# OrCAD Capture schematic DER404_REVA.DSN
size B; title: 72V / 115mA    A19 application; rev: A; note: <Doc>
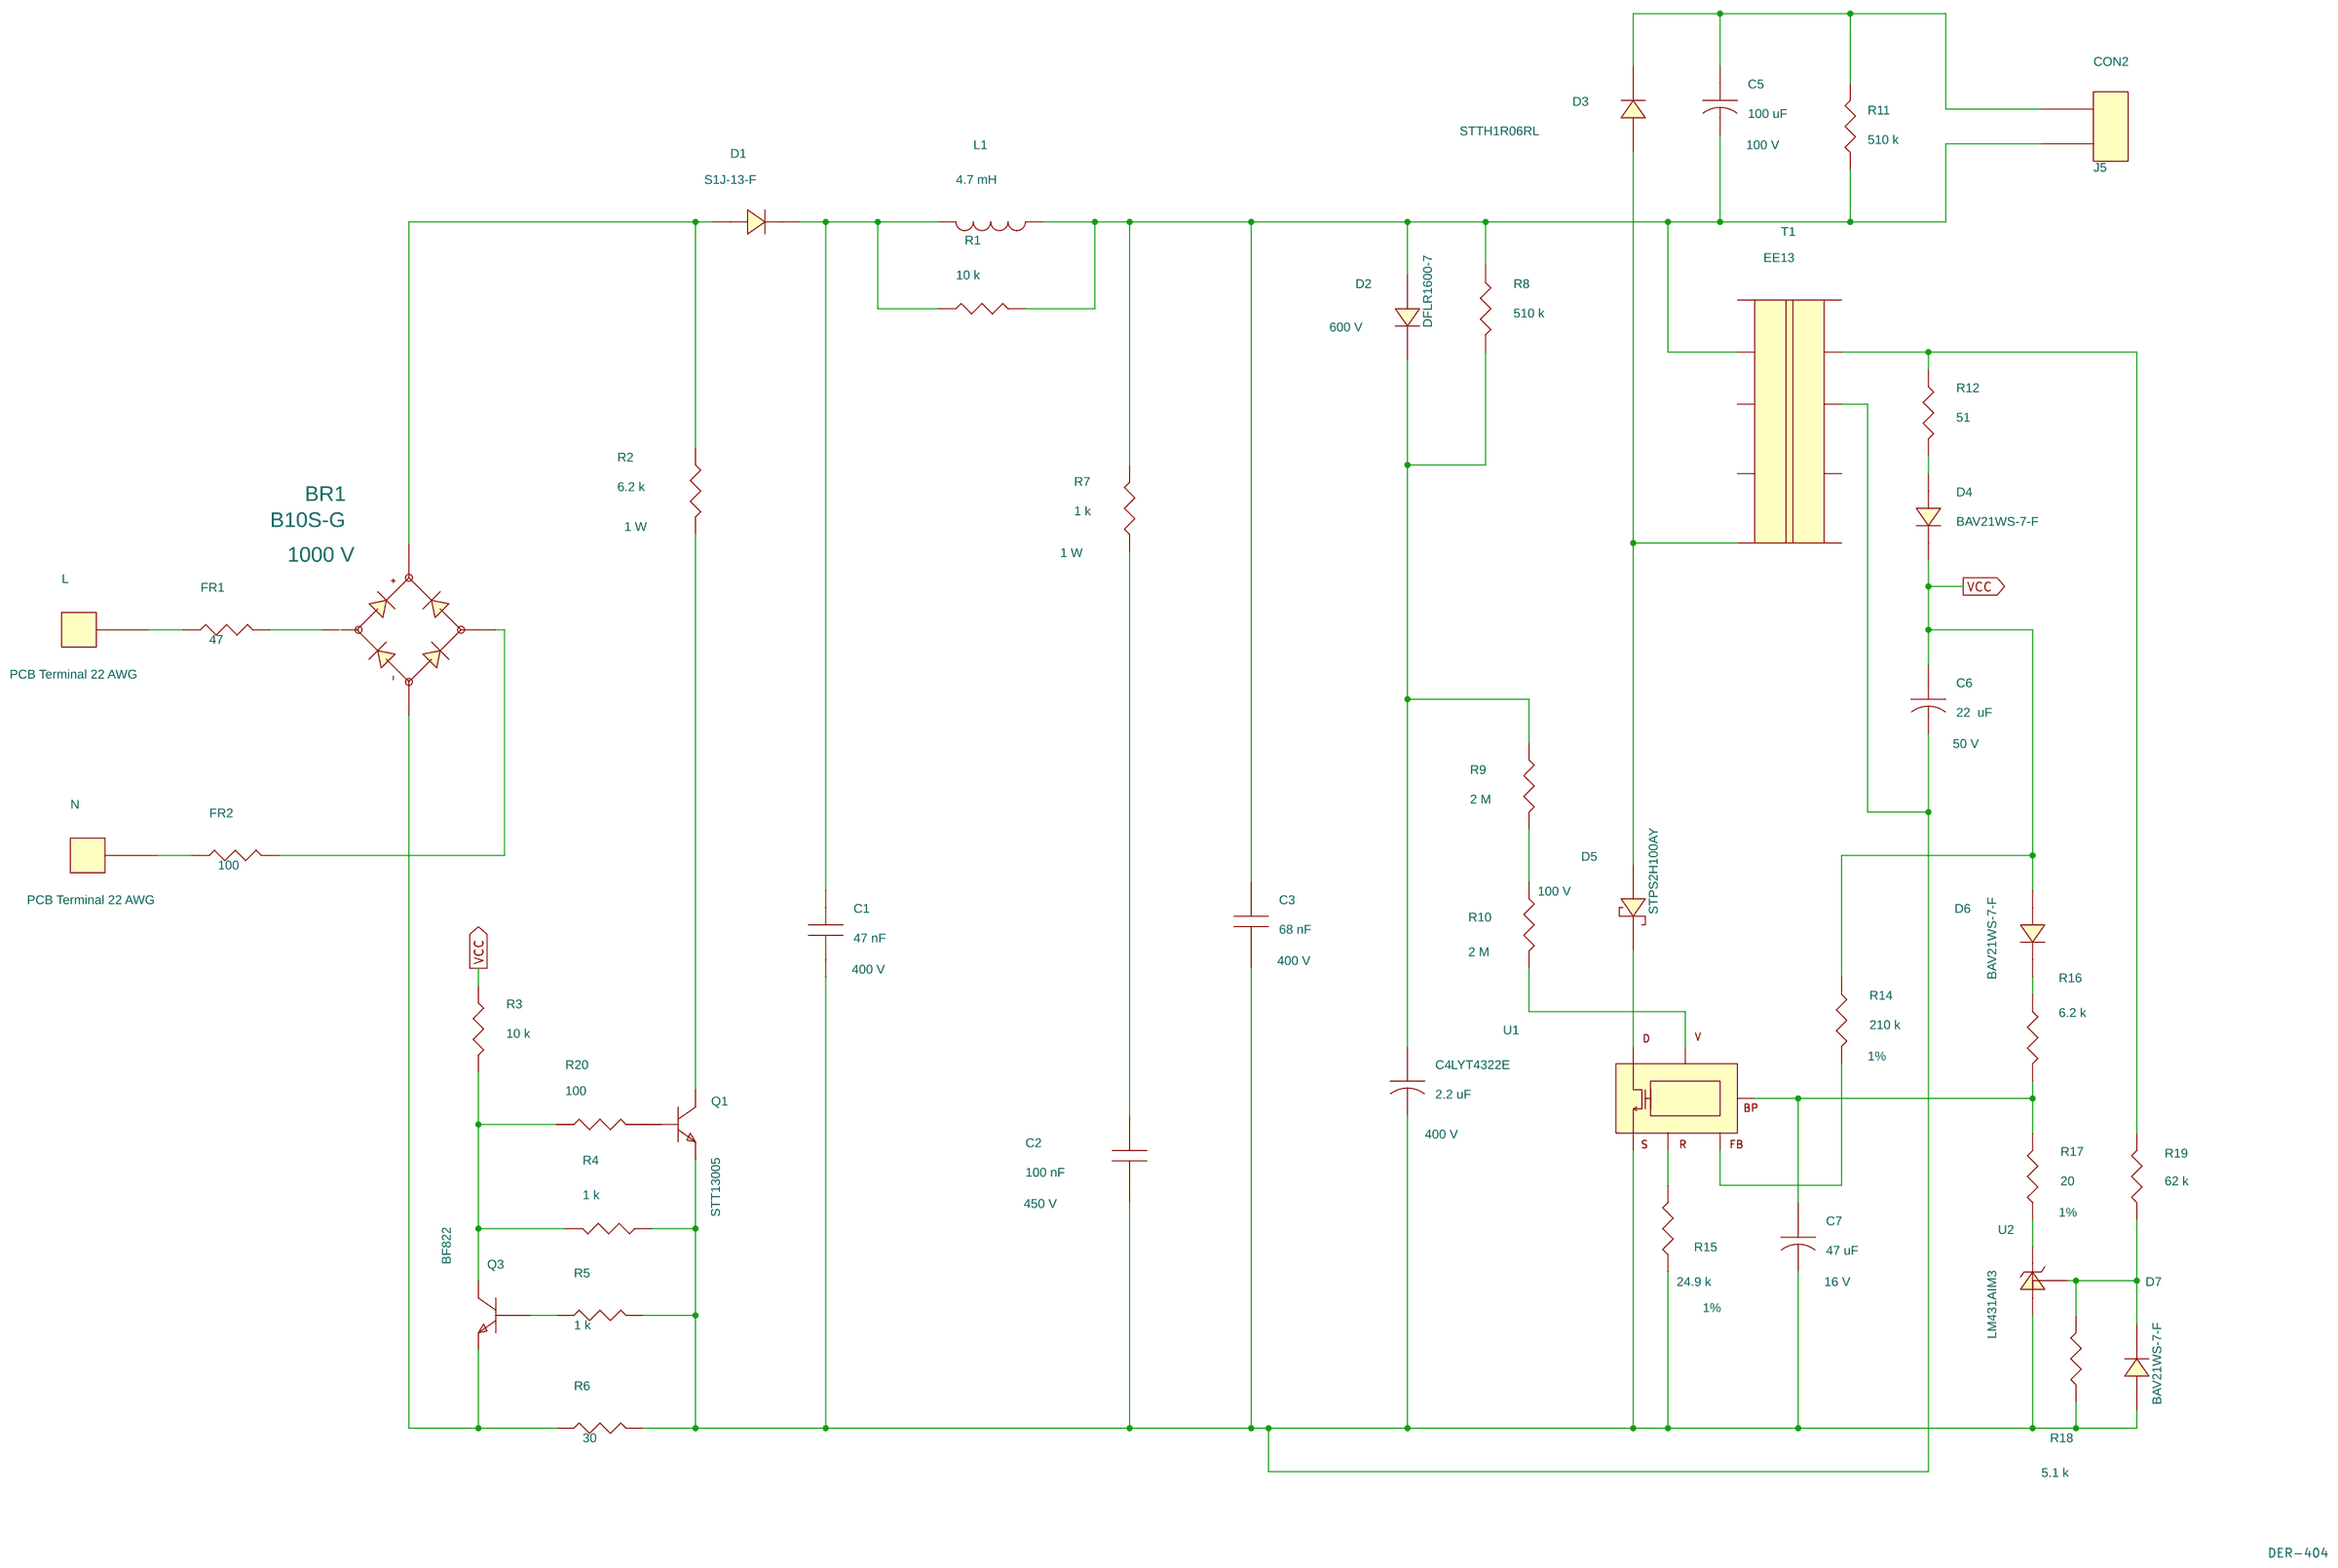
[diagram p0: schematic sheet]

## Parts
BR1  B10S-G  [pismsoic4]
C1  47 nF  [pinpcaprad500x240400040]
C2  100 nF  [pinpcaprad440x200300040]
C3  68 nF  [pinpcaprad500x240400040]
C4  2.2 uF  [pipolcapcyld250ls100030]
C5  100 uF  [pipolcapcyld400ls200040]
C6  22  uF  [pipolcapclyd200ls80030]
C7  47 uF  [pipolcapclyd200ls80030]
D1  S1J-13-F  [pismdsma]
D2  DFLR1600-7  [pismddflr120012]
D3  STTH1R06RL  [pidv200x110x040do41]
D4  BAV21WS-7-F  [pismsod323]
D5  STPS2H100AY  [pismdsma]
D6  BAV21WS-7-F  [pismsod323]
D7  BAV21WS-7-F  [pismsod323]
FR1  47  [PI_2W_VRES240LS200D040]
FR2  100  [pi1wvresd120ls200d040]
J5  CON2  [pi_conn_lee_leds]
L  PCB Terminal 22 AWG  [pi_hole_22awg]
L1  4.7 mH  [pi_choke_450hx375ls197d030]
N  PCB Terminal 22 AWG  [pi_hole_22awg]
Q1  STT13005  [pi_to126_vf1-321]
Q3  BF822  [pismsot23132]
R1  10 k  [pismr0805]
R2  6.2 k  [pi1wresd200ls725d040]
R3  10 k  [pismr1206]
R4  1 k  [pismr0805]
R5  1 k  [pismr0805]
R6  30  [pi1wvresd120ls200d040]
R7  1 k  [pi1wresd200ls725d040]
R8  510 k  [pismr1206]
R9  2 M  [pismr1206]
R10  2 M  [pismr1206]
R11  510 k  [pismr1206]
R12  51  [pismr1206]
R14  210 k  [pismr1206]
R15  24.9 k  [pismr0805]
R16  6.2 k  [pismr0603]
R17  20  [pismr1206]
R18  5.1 k  [pismr0805]
R19  62 k  [pismr0805]
R20  100  [pismr0603]
T1  EE13  [pi_bobbin_ee13v_10p]
U1  LYT4322E  [piicesip76th]
U2  LM431AIM3  [pismsot23123]

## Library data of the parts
BR1 = DIODE_BRIDGE_~~+-: Disp_Voltage: 1000 V; Part Number: 15-00818-00; ROOM: 1
C1 = CAP_NP: Disp_Voltage: 400 V; Part Number: 20-00365-00; Voltage: 400 V
C2 = CAP_NP: ALT_SYMBOLS: pinpcaprad440x200300040h; Disp_Voltage: 450 V; FPLIST: pinpcaprad440x200300040,pinpcaprad440x200300040h; Part Number: 20-08690-00; ROOM: 1; Voltage: 450 V
C3 = CAP_NP: Disp_Voltage: 400 V; Part Number: 20-00366-00; Voltage: 400 V
C4 = CAP_POL: ALT_SYMBOLS: pipolcapcyld250ls100030h; Disp_Voltage: 400 V; Part Number: 20-01008-00; Voltage: 400 V
C5 = CAP_POL: ALT_SYMBOLS: pipolcapcyld400ls200040800h; Disp_Voltage: 100 V; FPLIST: pipolcapcyld400ls200040,pipolcapcyld400ls200040800h; Part Number: 20-00954-00; Voltage: 100 V
C6 = CAP_POL: ALT_SYMBOLS: pipolcapclyd200ls80030h; Disp_Voltage: 50 V; FPLIST: pipolcapclyd200ls80030,pipolcapclyd200ls80030h; Part Number: 20-00950-00; Voltage: 50 V
C7 = CAP_POL: Disp_Voltage: 16 V; Part Number: 20-00804-00; Voltage: 16 V
D1 = DIODE: Part Number: 15-01034-00
D2 = DIODE: Disp_Voltage: 600 V; Part Number: 15-00826-00
D3 = DIODE: ALT_SYMBOLS: pidax475x125040do41,pidax390x125040do41; FPLIST: pidv200x110x040do41,pidax475x125040do41,pidax390x125040do41; Part Number: 15-01031-00
D4 D6 D7 = DIODE: Part Number: 15-00385-00
D5 = DIODE_SCHOTTKY: Disp_Voltage: 100 V; Part Number: 15-00985-00
FR1 = R: ALT_SYMBOLS: PI_2W_RES240LS500D040,pi_2w_resd145ls455d040; Disp_Power: 2 W; FPLIST: PI_2W_VRES240LS200D040,PI_2W_RES240LS500D040,pi_2w_resd145ls455d040; PCB Editor PCBFP: pi12wvresd180ls150d040,pi12wvresd180ls200d040,pi12wvresd180ls250d040,pi12wresd180ls675d040; Part Number: 05-05559-00; Tol: 5%
FR2 = R: ALT_SYMBOLS: pi1wvresd120ls200d040,pi1wvresd120ls300d040,pi1wvresd200ls200d040,pi1wvresd200ls300d040,pi1wvresd200ls350d040; Disp_Power: 1 W; FPLIST: pi1wresd200ls725d040,pi1wvresd120ls200d040,pi1wvresd120ls300d040,pi1wvresd200ls200d040,pi1wvresd200ls300d040,pi1wvresd200ls350d040; PCB Editor PCBFP: pi12wvresd180ls150d040,pi12wvresd180ls200d040,pi12wvresd180ls250d040,pi12wresd180ls675d040; Part Number: 05-02828-00; Tol: 5%
J5 = CON2: Part Number: 35-00252-00
L N = TERM_1Pin: Part Number: 35-00008-00
L1 = INDUCTOR: FPLIST: pi_choke_450hx375ls197d030,pi_choke_450hx375ls197d030_h; Part Number: 30-00329-00; ROOM: 1
Q1 = NPN_BCE: ALT_SYMBOLS: pi_to126-321; FPLIST: PITO126VF1,PITO126VF1; Part Number: 55-00085-00
Q3 = NPN_BEC: Part Number: 55-00102-00
R1 = R: Part Number: 05-01543-00; ROOM: 1
R2 = R: ALT_SYMBOLS: pi1wvresd120ls200d040,pi1wvresd120ls300d040,pi1wvresd200ls200d040,pi1wvresd200ls300d040,pi1wvresd200ls350d040; Disp_Power: 1 W; FPLIST: pi1wresd200ls725d040,pi1wvresd120ls200d040,pi1wvresd120ls300d040,pi1wvresd200ls200d040,pi1wvresd200ls300d040,pi1wvresd200ls350d040; Part Number: 05-02871-00
R3 = R: Part Number: 05-01376-00
R4 R5 = R: Part Number: 05-01519-00
R6 = R: ALT_SYMBOLS: pi1wvresd120ls200d040,pi1wvresd120ls300d040,pi1wvresd200ls200d040,pi1wvresd200ls300d040,pi1wvresd200ls350d040; Disp_Power: 1 W; FPLIST: pi1wresd200ls725d040,pi1wvresd120ls200d040,pi1wvresd120ls300d040,pi1wvresd200ls200d040,pi1wvresd200ls300d040,pi1wvresd200ls350d040; PCB Editor PCBFP: pi12wvresd180ls150d040,pi12wvresd180ls200d040,pi12wvresd180ls250d040,pi12wresd180ls675d040; Part Number: 05-02815-00; Tol: 5%
R7 = R: ALT_SYMBOLS: pi1wvresd120ls200d040,pi1wvresd120ls300d040,pi1wvresd200ls200d040,pi1wvresd200ls300d040,pi1wvresd200ls350d040; Disp_Power: 1 W; FPLIST: pi1wresd200ls725d040,pi1wvresd120ls200d040,pi1wvresd120ls300d040,pi1wvresd200ls200d040,pi1wvresd200ls300d040,pi1wvresd200ls350d040; Part Number: 05-02852-00; ROOM: 1
R8 R11 = R: Part Number: 05-01417-00
R9 R10 = R: Part Number: 05-01428-00
R12 = R: Part Number: 05-01321-00
R14 = R: Disp_Tol: 1%; Part Number: 05-00416-00
R15 = R: Disp_Tol: 1%; Part Number: 05-00722-00
R16 = R: Part Number: 05-01707-00
R17 = R: Disp_Tol: 1%; Part Number: 05-00030-00
R18 = R: Part Number: 05-01536-00
R19 = R: Part Number: 05-01562-00
R20 = R: Part Number: 05-01664-00
T1 = BEE13_10PINS_GENERIC: Part Number: 25-01023-00
U1 = LNK40X_eSIP: Part Number: 10-00730-00
U2 = TL431_SOT-23_CAR: Part Number: 45-00144-00

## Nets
VCC: C6.1 D4.1 D6.2 R3.2 R14.1
N1678526: C1.2 C2.2 C3.2 C4.2 C6.2 C7.2 D7.2 Q1.3(EMITTER) R4.1 R5.1 R6.1 R15.1 R18.1 T1.8 U1.5(S) U2.2(A)
N2200496: C4.1 D2.1 R8.2 R9.1
N2229506: BR1.4 Q3.2(EMITTER) R6.2
N2302506: FR1.2 L.1
N2488295: BR1.2 FR1.1
N2491459: C7.1 R16.2 R17.2 U1.4(BP)
N2492720: D5.1 U1.7(D)
N2492766: R15.2 U1.1(R)
N2493445: C3.1 C5.2 D2.2 J5.1 L1.1 R1.2 R7.1 R8.1 R11.1 T1.2
N2532048: R14.2 U1.3(FB)
N2536376: BR1.1 FR2.1
N2538393: BR1.3 D1.2 R2.2
N3672068: C5.1 D3.1 J5.2 R11.2
N3681742: C1.1 D1.1 L1.2 R1.1
N3711440: D3.2 D5.2 T1.5
N3718886: R17.1 U2.1(C)
N3740281: R10.2 U1.2(V)
N3826642: C2.1 R7.2
N3829350: FR2.2 N.1
N3832527: D7.1 R18.2 R19.1 U2.3(VREF)
N3833167: R12.1 R19.2 T1.9
N3837669: R9.2 R10.1
N3843499: Q3.1(BASE) R5.2
N3843511: Q3.3(COLLECTOR) R3.1 R4.2 R20.1
N3845096: Q1.2(COLLECTOR) R2.1
N3872531: D4.2 R12.2
N3873174: D6.1 R16.1
N3878973: Q1.1(BASE) R20.2

Not connected (* = marked no-connect by the designer): T1 1 3 4 6 7 10

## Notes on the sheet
- DER-404
